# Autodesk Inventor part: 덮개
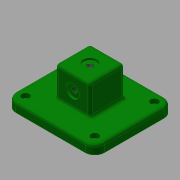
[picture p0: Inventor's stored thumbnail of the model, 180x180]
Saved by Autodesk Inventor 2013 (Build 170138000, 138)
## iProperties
Created: 2017-08
Part Number: 덮개
Material: 알루미늄 6061
Document SubType Name: Modeling
Designer: mduedu
Density: 1 g/cm^3
Author: mduedu
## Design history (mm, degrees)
sketch "스케치1"
  geometry: L1 (46, -41)-(-46, -41); L2 (-46, -41)-(-46, 41); L3 (-46, 41)-(46, 41); L4 (46, 41)-(46, -41); 1 further point
  constraints: 8 end point, 2 parallel, 1 horizontal, 1 perpendicular
  dimensions: "d0" = 92 distance of L2.end L3.end; "d2" = 82 distance of L1.end L2.end; "d3" = 41 distance from line of L3 point (0, 0) (= 0.5 x d2); "d4" = 46 distance from line of point (0, 0) L4 (= 0.5 x d0)
extrude "돌출1" new body sketch "스케치1" distance "d5" = 10; taper "d6" = 0 deg
sketch "스케치2"
  geometry: L1 (-18, -18)-(18, -18); L2 (18, -18)-(18, 18); L3 (18, 18)-(-18, 18); L4 (-18, 18)-(-18, -18); L5 (-18, -18)-(18, 18); L6 (18, -18)-(-18, 18); 1 further point
  constraints: 12 end point, 2 midpoint, 2 parallel, 2 perpendicular, 1 horizontal
  dimensions: "d7" = 36 distance of L2.end L3.end
extrude "돌출2" join sketch "스케치2" distance "d9" = 32; taper "d10" = 0 deg
sketch "스케치3"
  geometry: L1 (-26, -26)-(26, -26); L2 (26, -26)-(26, 26); L3 (26, 26)-(-26, 26); L4 (-26, 26)-(-26, -26); L5 (-26, -26)-(26, 26); L6 (26, -26)-(-26, 26); 1 further point
  constraints: 12 end point, 2 midpoint, 2 parallel, 2 perpendicular, 1 horizontal
  dimensions: "d11" = 52 distance of L3.end L2.end
extrude "돌출3" join sketch "스케치3" distance "d12" = 6; taper "d13" = 0 deg
sketch "스케치4"
  geometry: L1 (-17, -17)-(17, -17); L2 (17, -17)-(17, 17); L3 (17, 17)-(-17, 17); L4 (-17, 17)-(-17, -17); L5 (-17, -17)-(17, 17); L6 (17, -17)-(-17, 17); 1 further point
  constraints: 12 end point, 2 midpoint, 2 parallel, 2 perpendicular, 1 horizontal
  dimensions: "d14" = 34 distance of L2.end L3.end
extrude "돌출4" cut sketch "스케치4" distance "d16" = 5; taper "d17" = 0 deg
sketch "스케치5"
  geometry: C1 r 9 at (0, 0); 1 further point
  constraints: 1 centre point, 1 coincident
  dimensions: "d18" = 18 diameter of C1
extrude "돌출5" cut sketch "스케치5" distance "d19" = 34; taper "d20" = 0 deg
sketch "스케치6"
  geometry: 2 further points
  constraints: 1 coincident
hole "구멍1" sketch "스케치6" at (0, 0) diameter "d21" = 5.917; stored, may be unused: countersink angle "d25" = 90 deg, drill point angle "d27" = 118 deg; dims "d22" = 6, "d23" = 14, "d24" = 2, "d26" = 8
sketch "스케치7"
  geometry: L1 (-28, -10)-(64, -10) reference; 3 further points
  constraints: 1 midpoint, 1 vertical alignment
  dimensions: "d47" = 26 distance from line of point (18, 16) L1
hole "구멍2" sketch "스케치7" at (18, 16) diameter "d29" = 5.917; stored, may be unused: countersink angle "d33" = 90 deg, drill point angle "d35" = 118 deg; dims "d30" = 6, "d31" = 14, "d32" = 2, "d34" = 8
fillet "모깎기1" dims "d36" = 10
fillet "모깎기2" dims "d37" = 3
fillet "모깎기3" dims "d38" = 3
fillet "모깎기4" dims "d39" = 3
fillet "모깎기5" dims "d40" = 3
chamfer "모따기1" distance "d41" = 1; stored, may be unused: second distance "d42" = 2, angle "d43" = 45 deg
fillet "모깎기6" dims "d44" = 3
fillet "모깎기7" dims "d45" = 3
fillet "모깎기8" dims "d46" = 3
sketch "스케치8"
  geometry: A1 r 10 centre (-36, -31) between (-46, -31) and (-36, -41) reference; A2 r 10 centre (-36, 31) between (-36, 41) and (-46, 31) reference; A3 r 10 centre (36, 31) between (46, 31) and (36, 41) reference; A4 r 10 centre (36, -31) between (36, -41) and (46, -31) reference; 5 further points
  constraints: 4 coincident
sketch "스케치9"
  geometry: 4 further points
  constraints: 4 other
hole "구멍3" sketch "스케치9" at (-36, -31), (-36, 31), (36, 31), (36, -31) diameter "d48" = 4.5; stored, may be unused: countersink angle "d52" = 90 deg, drill point angle "d54" = 0 deg; dims "d49" = 6, "d50" = 8, "d51" = 4.6, "d53" = 8
node "솔리드1"
